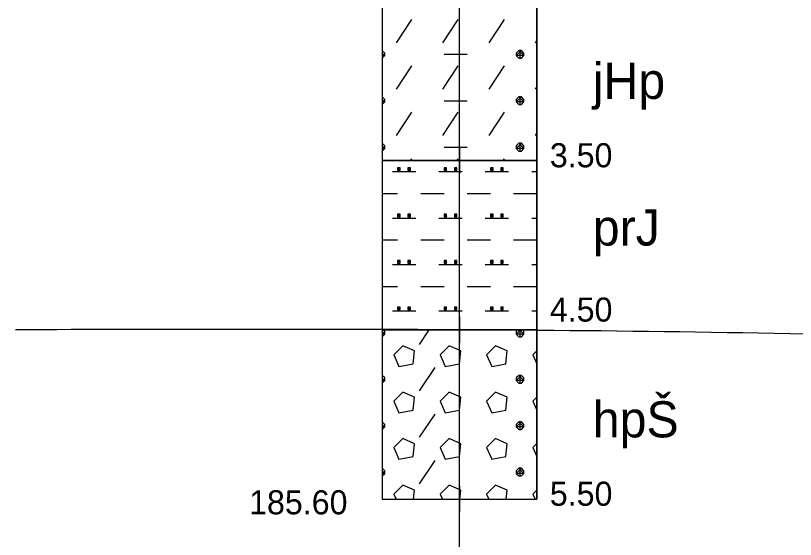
# Model space of a CAD drawing. Extents: x 3042 to 4120, y 576 to 2694.
# Drawn here: x 3246.88 to 3269.93, y 743.05 to 758.52 of the extents above; entities that cross this region are included whole.
import ezdxf

# ---------------------------------------------------------------- set-up
doc = ezdxf.new("R2010")
doc.units = 0
for name, color, linetype in [('17', 7, 'Continuous'), ('18', 7, 'Continuous'), ('51', 7, 'Continuous'), ('52', 7, 'Continuous'), ('53', 7, 'Continuous'), ('56', 7, 'Continuous'), ('pomocna', 7, 'Continuous'), ('rozhraní', 7, 'Continuous')]:
    doc.layers.add(name, color=color, linetype=linetype)

msp = doc.modelspace()

# ---------------------------------------------------------------- linework, layer by layer
at = {"layer": '18'}
for p, q in [((3260.007, 744.241), (3260.007, 771.741)), ((3260.007, 744.622), (3260.007, 743.86)), ((3259.626, 744.241), (3260.388, 744.241))]:
    msp.add_line(p, q, dxfattribs=at)
at = {"layer": '51'}
for p, q in [((3258.137, 757.724), (3258.594, 758.41)), ((3259.509, 757.724), (3259.966, 758.41)), ((3260.88, 757.724), (3261.337, 758.41)), ((3262.252, 757.724), (3262.293, 757.785)), ((3257.718, 757.496), (3257.718, 757.496)), ((3259.547, 757.381), (3260.233, 757.381)), ((3261.795, 757.267), (3261.795, 757.496)), ((3258.137, 756.353), (3258.594, 757.038)), ((3259.509, 756.353), (3259.966, 757.038)), ((3260.88, 756.353), (3261.337, 757.038)), ((3262.252, 756.353), (3262.293, 756.414)), ((3257.718, 756.124), (3257.718, 756.124)), ((3259.547, 756.01), (3260.233, 756.01)), ((3261.795, 755.895), (3261.795, 756.124)), ((3258.137, 754.981), (3258.594, 755.667)), ((3259.509, 754.981), (3259.966, 755.667)), ((3260.88, 754.981), (3261.337, 755.667)), ((3262.252, 754.981), (3262.293, 755.042)), ((3257.718, 754.752), (3257.718, 754.752)), ((3261.795, 754.524), (3261.795, 754.752)), ((3259.547, 754.638), (3260.233, 754.638)), ((3258.558, 754.241), (3258.594, 754.295)), ((3259.93, 754.241), (3259.966, 754.295)), ((3261.301, 754.241), (3261.337, 754.295)), ((3258.023, 753.914), (3258.709, 753.914)), ((3259.394, 753.914), (3260.08, 753.914)), ((3260.766, 753.914), (3261.452, 753.914)), ((3262.138, 753.914), (3262.293, 753.914)), ((3257.721, 753.266), (3258.175, 753.266)), ((3258.861, 753.266), (3259.547, 753.266)), ((3260.233, 753.266), (3260.918, 753.266)), ((3261.604, 753.266), (3262.29, 753.266)), ((3258.023, 752.543), (3258.709, 752.543)), ((3259.394, 752.543), (3260.08, 752.543)), ((3260.766, 752.543), (3261.452, 752.543)), ((3262.138, 752.543), (3262.293, 752.543)), ((3257.721, 751.895), (3258.175, 751.895)), ((3258.861, 751.895), (3259.547, 751.895)), ((3260.233, 751.895), (3260.918, 751.895)), ((3261.604, 751.895), (3262.29, 751.895)), ((3258.023, 751.171), (3258.709, 751.171)), ((3259.394, 751.171), (3260.08, 751.171)), ((3260.766, 751.171), (3261.452, 751.171)), ((3262.138, 751.171), (3262.293, 751.171)), ((3257.721, 750.523), (3258.175, 750.523)), ((3258.861, 750.523), (3259.547, 750.523)), ((3260.233, 750.523), (3260.918, 750.523)), ((3261.604, 750.523), (3262.29, 750.523)), ((3258.023, 749.799), (3258.709, 749.799)), ((3259.394, 749.799), (3260.08, 749.799)), ((3260.766, 749.799), (3261.452, 749.799)), ((3262.138, 749.799), (3262.293, 749.799)), ((3258.823, 748.809), (3259.111, 749.241)), ((3261.795, 749.037), (3261.795, 749.241)), ((3262.293, 748.621), (3262.176, 748.504)), ((3262.176, 748.504), (3262.293, 748.24)), ((3258.823, 747.437), (3259.28, 748.123)), ((3257.718, 747.894), (3257.718, 747.894)), ((3261.795, 747.666), (3261.795, 747.894)), ((3262.293, 747.249), (3262.176, 747.132)), ((3262.176, 747.132), (3262.293, 746.869)), ((3258.823, 746.066), (3259.28, 746.751)), ((3257.718, 746.523), (3257.718, 746.523)), ((3261.795, 746.294), (3261.795, 746.523)), ((3262.293, 745.878), (3262.176, 745.761)), ((3262.176, 745.761), (3262.293, 745.497)), ((3258.823, 744.694), (3259.28, 745.38)), ((3257.718, 745.151), (3257.718, 745.151)), ((3261.795, 744.923), (3261.795, 745.151)), ((3258.061, 744.389), (3258.127, 744.241)), ((3259.432, 744.389), (3259.498, 744.241)), ((3260.804, 744.389), (3260.87, 744.241)), ((3262.293, 744.506), (3262.176, 744.389)), ((3262.176, 744.389), (3262.242, 744.241))]:
    msp.add_line(p, q, dxfattribs=at)
for points in [[(3257.721, 754.241), (3262.293, 754.241), (3262.293, 759.241), (3257.721, 759.241)], [(3257.721, 749.241), (3262.293, 749.241), (3262.293, 754.241), (3257.721, 754.241)], [(3257.721, 744.241), (3262.293, 744.241), (3262.293, 749.241), (3257.721, 749.241)]]:
    msp.add_lwpolyline(points, close=True, dxfattribs=at)
for points in [[(3257.718, 757.267), (3257.718, 757.267), (3257.794, 757.343), (3257.794, 757.419), (3257.718, 757.496), (3257.718, 757.496)], [(3257.721, 757.417), (3257.794, 757.343), (3257.721, 757.343)], [(3261.757, 757.496), (3261.68, 757.419), (3261.68, 757.343), (3261.757, 757.267), (3261.833, 757.267), (3261.909, 757.343), (3261.909, 757.419), (3261.833, 757.496), (3261.757, 757.496), (3261.909, 757.343), (3261.68, 757.343), (3261.833, 757.496)], [(3257.718, 755.895), (3257.718, 755.895), (3257.794, 755.972), (3257.794, 756.048), (3257.718, 756.124), (3257.718, 756.124)], [(3257.721, 756.045), (3257.794, 755.972), (3257.721, 755.972)], [(3261.757, 756.124), (3261.68, 756.048), (3261.68, 755.972), (3261.757, 755.895), (3261.833, 755.895), (3261.909, 755.972), (3261.909, 756.048), (3261.833, 756.124), (3261.757, 756.124), (3261.909, 755.972), (3261.68, 755.972), (3261.833, 756.124)], [(3257.718, 754.524), (3257.718, 754.524), (3257.794, 754.6), (3257.794, 754.676), (3257.718, 754.752), (3257.718, 754.752)], [(3261.757, 754.752), (3261.68, 754.676), (3261.68, 754.6), (3261.757, 754.524), (3261.833, 754.524), (3261.909, 754.6), (3261.909, 754.676), (3261.833, 754.752), (3261.757, 754.752), (3261.909, 754.6), (3261.68, 754.6), (3261.833, 754.752)], [(3257.721, 754.673), (3257.794, 754.6), (3257.721, 754.6)], [(3258.175, 754.028), (3258.175, 753.952), (3258.251, 753.952), (3258.251, 754.028), (3258.175, 754.028), (3258.251, 753.952)], [(3258.48, 754.028), (3258.48, 753.952), (3258.556, 753.952), (3258.556, 754.028), (3258.48, 754.028), (3258.556, 753.952)], [(3259.547, 754.028), (3259.547, 753.952), (3259.623, 753.952), (3259.623, 754.028), (3259.547, 754.028), (3259.623, 753.952)], [(3259.852, 754.028), (3259.852, 753.952), (3259.928, 753.952), (3259.928, 754.028), (3259.852, 754.028), (3259.928, 753.952)], [(3260.918, 754.028), (3260.918, 753.952), (3260.995, 753.952), (3260.995, 754.028), (3260.918, 754.028), (3260.995, 753.952)], [(3261.223, 754.028), (3261.223, 753.952), (3261.299, 753.952), (3261.299, 754.028), (3261.223, 754.028), (3261.299, 753.952)], [(3262.29, 754.028), (3262.29, 753.952), (3262.293, 753.952)], [(3262.293, 754.028), (3262.29, 754.028), (3262.293, 754.026)], [(3258.175, 752.657), (3258.175, 752.581), (3258.251, 752.581), (3258.251, 752.657), (3258.175, 752.657), (3258.251, 752.581)], [(3258.48, 752.657), (3258.48, 752.581), (3258.556, 752.581), (3258.556, 752.657), (3258.48, 752.657), (3258.556, 752.581)], [(3259.547, 752.657), (3259.547, 752.581), (3259.623, 752.581), (3259.623, 752.657), (3259.547, 752.657), (3259.623, 752.581)], [(3259.852, 752.657), (3259.852, 752.581), (3259.928, 752.581), (3259.928, 752.657), (3259.852, 752.657), (3259.928, 752.581)], [(3260.918, 752.657), (3260.918, 752.581), (3260.995, 752.581), (3260.995, 752.657), (3260.918, 752.657), (3260.995, 752.581)], [(3261.223, 752.657), (3261.223, 752.581), (3261.299, 752.581), (3261.299, 752.657), (3261.223, 752.657), (3261.299, 752.581)], [(3262.29, 752.657), (3262.29, 752.581), (3262.293, 752.581)], [(3262.293, 752.657), (3262.29, 752.657), (3262.293, 752.654)], [(3258.175, 751.285), (3258.175, 751.209), (3258.251, 751.209), (3258.251, 751.285), (3258.175, 751.285), (3258.251, 751.209)], [(3258.48, 751.285), (3258.48, 751.209), (3258.556, 751.209), (3258.556, 751.285), (3258.48, 751.285), (3258.556, 751.209)], [(3259.547, 751.285), (3259.547, 751.209), (3259.623, 751.209), (3259.623, 751.285), (3259.547, 751.285), (3259.623, 751.209)], [(3259.852, 751.285), (3259.852, 751.209), (3259.928, 751.209), (3259.928, 751.285), (3259.852, 751.285), (3259.928, 751.209)], [(3260.918, 751.285), (3260.918, 751.209), (3260.995, 751.209), (3260.995, 751.285), (3260.918, 751.285), (3260.995, 751.209)], [(3261.223, 751.285), (3261.223, 751.209), (3261.299, 751.209), (3261.299, 751.285), (3261.223, 751.285), (3261.299, 751.209)], [(3262.29, 751.285), (3262.29, 751.209), (3262.293, 751.209)], [(3262.293, 751.285), (3262.29, 751.285), (3262.293, 751.282)], [(3258.175, 749.914), (3258.175, 749.837), (3258.251, 749.837), (3258.251, 749.914), (3258.175, 749.914), (3258.251, 749.837)], [(3258.48, 749.914), (3258.48, 749.837), (3258.556, 749.837), (3258.556, 749.914), (3258.48, 749.914), (3258.556, 749.837)], [(3259.547, 749.914), (3259.547, 749.837), (3259.623, 749.837), (3259.623, 749.914), (3259.547, 749.914), (3259.623, 749.837)], [(3259.852, 749.914), (3259.852, 749.837), (3259.928, 749.837), (3259.928, 749.914), (3259.852, 749.914), (3259.928, 749.837)], [(3260.918, 749.914), (3260.918, 749.837), (3260.995, 749.837), (3260.995, 749.914), (3260.918, 749.914), (3260.995, 749.837)], [(3261.223, 749.914), (3261.223, 749.837), (3261.299, 749.837), (3261.299, 749.914), (3261.223, 749.914), (3261.299, 749.837)], [(3262.29, 749.914), (3262.29, 749.837), (3262.293, 749.837)], [(3262.293, 749.914), (3262.29, 749.914), (3262.293, 749.911)], [(3257.718, 749.037), (3257.718, 749.037), (3257.794, 749.114), (3257.794, 749.19), (3257.743, 749.241)], [(3261.731, 749.241), (3261.68, 749.19), (3261.68, 749.114), (3261.757, 749.037), (3261.833, 749.037), (3261.909, 749.114), (3261.909, 749.19), (3261.858, 749.241)], [(3261.782, 749.241), (3261.909, 749.114), (3261.68, 749.114), (3261.808, 749.241)], [(3257.721, 749.187), (3257.794, 749.114), (3257.721, 749.114)], [(3258.061, 748.504), (3258.213, 748.161), (3258.632, 748.237), (3258.67, 748.618), (3258.328, 748.771), (3258.061, 748.504)], [(3259.432, 748.504), (3259.585, 748.161), (3260.004, 748.237), (3260.042, 748.618), (3259.699, 748.771), (3259.432, 748.504)], [(3260.804, 748.504), (3260.956, 748.161), (3261.376, 748.237), (3261.414, 748.618), (3261.071, 748.771), (3260.804, 748.504)], [(3257.718, 747.666), (3257.718, 747.666), (3257.794, 747.742), (3257.794, 747.818), (3257.718, 747.894), (3257.718, 747.894)], [(3261.757, 747.894), (3261.68, 747.818), (3261.68, 747.742), (3261.757, 747.666), (3261.833, 747.666), (3261.909, 747.742), (3261.909, 747.818), (3261.833, 747.894), (3261.757, 747.894), (3261.909, 747.742), (3261.68, 747.742), (3261.833, 747.894)], [(3257.721, 747.815), (3257.794, 747.742), (3257.721, 747.742)], [(3258.061, 747.132), (3258.213, 746.789), (3258.632, 746.866), (3258.67, 747.247), (3258.328, 747.399), (3258.061, 747.132)], [(3259.432, 747.132), (3259.585, 746.789), (3260.004, 746.866), (3260.042, 747.247), (3259.699, 747.399), (3259.432, 747.132)], [(3260.804, 747.132), (3260.956, 746.789), (3261.376, 746.866), (3261.414, 747.247), (3261.071, 747.399), (3260.804, 747.132)], [(3257.718, 746.294), (3257.718, 746.294), (3257.794, 746.37), (3257.794, 746.447), (3257.718, 746.523), (3257.718, 746.523)], [(3261.757, 746.523), (3261.68, 746.447), (3261.68, 746.37), (3261.757, 746.294), (3261.833, 746.294), (3261.909, 746.37), (3261.909, 746.447), (3261.833, 746.523), (3261.757, 746.523), (3261.909, 746.37), (3261.68, 746.37), (3261.833, 746.523)], [(3257.721, 746.444), (3257.794, 746.37), (3257.721, 746.37)], [(3258.061, 745.761), (3258.213, 745.418), (3258.632, 745.494), (3258.67, 745.875), (3258.328, 746.027), (3258.061, 745.761)], [(3259.432, 745.761), (3259.585, 745.418), (3260.004, 745.494), (3260.042, 745.875), (3259.699, 746.027), (3259.432, 745.761)], [(3260.804, 745.761), (3260.956, 745.418), (3261.376, 745.494), (3261.414, 745.875), (3261.071, 746.027), (3260.804, 745.761)], [(3257.718, 744.923), (3257.718, 744.923), (3257.794, 744.999), (3257.794, 745.075), (3257.718, 745.151), (3257.718, 745.151)], [(3257.721, 745.072), (3257.794, 744.999), (3257.721, 744.999)], [(3261.757, 745.151), (3261.68, 745.075), (3261.68, 744.999), (3261.757, 744.923), (3261.833, 744.923), (3261.909, 744.999), (3261.909, 745.075), (3261.833, 745.151), (3261.757, 745.151), (3261.909, 744.999), (3261.68, 744.999), (3261.833, 745.151)], [(3258.644, 744.241), (3258.67, 744.503), (3258.328, 744.656), (3258.061, 744.389)], [(3260.016, 744.241), (3260.042, 744.503), (3259.699, 744.656), (3259.432, 744.389)], [(3261.387, 744.241), (3261.414, 744.503), (3261.071, 744.656), (3260.804, 744.389)]]:
    msp.add_lwpolyline(points, dxfattribs=at)
at = {"layer": '53'}
for p, q in [((3257.721, 771.741), (3257.721, 744.241)), ((3262.293, 771.741), (3262.293, 744.241)), ((3257.721, 754.241), (3262.293, 754.241)), ((3257.721, 749.241), (3262.293, 749.241)), ((3257.721, 744.241), (3262.293, 744.241))]:
    msp.add_line(p, q, dxfattribs=at)
at = {"layer": '56'}
for p, q in [((3260.007, 754.622), (3260.007, 753.86)), ((3259.626, 754.241), (3260.388, 754.241)), ((3260.007, 749.622), (3260.007, 748.86)), ((3259.626, 749.241), (3260.388, 749.241)), ((3260.007, 744.622), (3260.007, 743.86)), ((3259.626, 744.241), (3260.388, 744.241))]:
    msp.add_line(p, q, dxfattribs=at)
at = {"layer": 'pomocna'}
msp.add_line((3260.007, 721.241), (3260.007, 773.941), dxfattribs=at)
at = {"layer": 'rozhraní'}
msp.add_spline([(3473.031, 745.954), (3425.231, 746.002), (3379.035, 745.039), (3364.156, 745.104), (3349.279, 745.526), (3319.528, 746.989), (3289.773, 748.528), (3260.007, 749.241), (3246.881, 749.241)], degree=3, dxfattribs=at)

# ---------------------------------------------------------------- texts
at = {"layer": '17'}
msp.add_text('185.60', height=0.7112, dxfattribs=at).set_placement((3253.784, 743.789))
at = {"layer": '52'}
for s, height, p in [('jHp', 1.0668, (3263.944, 756.063)), ('3.50', 0.7112, (3262.674, 754.043)), ('prJ', 1.0668, (3263.944, 751.73)), ('4.50', 0.7112, (3262.674, 749.484)), ('hpŠ', 1.0668, (3263.944, 746.063)), ('5.50', 0.7112, (3262.674, 744.043))]:
    msp.add_text(s, height=height, dxfattribs=at).set_placement(p)

doc.saveas('drawing.dxf')
